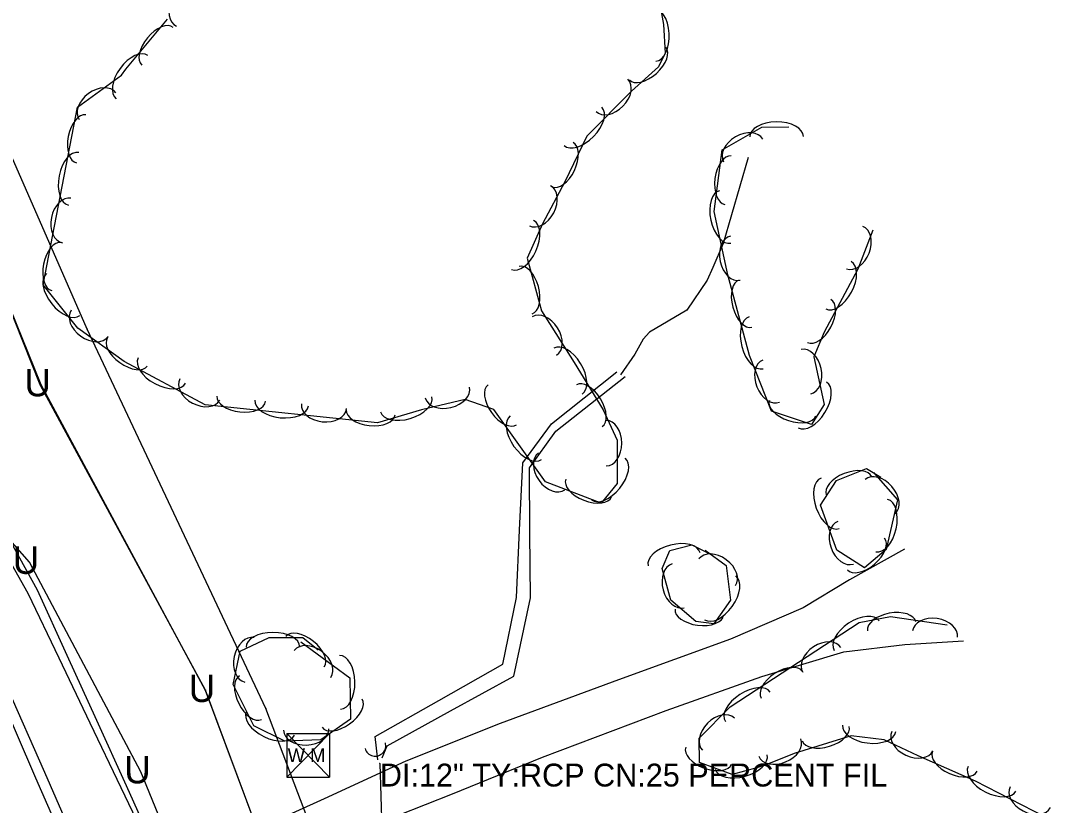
# Model space of a CAD drawing. Extents: x 954793 to 988390, y 1867850 to 1924428.
# Drawn here: x 964997.6 to 965222.6, y 1899765.7 to 1899937.2 of the extents above; entities that cross this region are included whole.
import ezdxf

# ---------------------------------------------------------------- set-up
doc = ezdxf.new("R2010")
doc.units = 0
for name, color, linetype in [('Default', 7, 'Continuous'), ('S_CROSS_DRAIN', 7, 'Continuous'), ('S_DITCHLINE', 7, 'Continuous'), ('S_DRG_PT_SYM', 7, 'Continuous'), ('S_DRIVEWAY', 7, 'Continuous'), ('S_EDGE_PAVEMENT', 7, 'Continuous'), ('S_FIBER_OPTIC_CABLE', 7, 'Continuous'), ('S_SHOULDER', 7, 'Continuous'), ('S_SIDE_DRAIN', 7, 'Continuous'), ('S_SIDE_DRAIN_ANNOT', 7, 'Continuous'), ('S_STREAM', 7, 'Continuous'), ('S_TREE', 7, 'Continuous'), ('S_UNDERGROUND_CABLE', 7, 'Continuous'), ('S_UTL_PT_SYM', 7, 'Continuous'), ('S_WATER_UTILITIES', 7, 'Continuous')]:
    doc.layers.add(name, color=color, linetype=linetype)

msp = doc.modelspace()

# ---------------------------------------------------------------- linework, layer by layer
at = {"layer": 'S_CROSS_DRAIN'}
msp.add_arc((965075.06, 1899778.75), 2.3, 195.7377, 16.0669, dxfattribs=at)
at = {"layer": 'S_DITCHLINE'}
for points in [[(965026.32, 1899755.36), (965019.55, 1899769.53), (965012.77, 1899783.69), (965006, 1899797.85), (964999.22, 1899812.02), (964991.34, 1899825.84), (964983.45, 1899839.67), (964977.86, 1899852.94), (964972.26, 1899866.21), (964966.67, 1899879.48), (964961.07, 1899892.75), (964954.42, 1899908.66), (964947.77, 1899924.57), (964941.11, 1899940.47), (964934.46, 1899956.38), (964927.09, 1899973.92), (964919.72, 1899991.46), (964912.35, 1900008.99), (964904.98, 1900026.53), (964899.8, 1900040.82)], [(965027.15, 1899755.7), (965020.67, 1899769.95), (965014.19, 1899784.21), (965007.71, 1899798.46), (965001.23, 1899812.71), (964993.53, 1899826.7), (964985.84, 1899840.69), (964979.82, 1899853.82), (964973.81, 1899866.96), (964967.79, 1899880.09), (964961.78, 1899893.22), (964955.75, 1899909.26), (964949.73, 1899925.3), (964943.7, 1899941.34), (964937.68, 1899957.38), (964929.93, 1899974.73), (964922.17, 1899992.09), (964914.42, 1900009.44), (964906.67, 1900026.79), (964900.96, 1900041.28)], [(965075.64, 1899775.62), (965075.01, 1899780.71), (965088.97, 1899788.63), (965102.94, 1899796.55), (965105.91, 1899811.09), (965106.6, 1899825.83), (965107.3, 1899840.57), (965113.6, 1899849.09), (965127.88, 1899860.44)], [(965076.56, 1899776.06), (965077.66, 1899778.73), (965091.51, 1899786.32), (965105.36, 1899793.9), (965108.95, 1899811.05), (965108.86, 1899825.24), (965108.76, 1899839.44), (965114.51, 1899847.45), (965129.67, 1899859.44)]]:
    msp.add_lwpolyline(points, dxfattribs=at)
at = {"layer": 'S_DRG_PT_SYM'}
msp.add_lwpolyline([(965076.07, 1899774.81), (965076.07, 1899774.86), (965076.07, 1899774.81), (965076.02, 1899774.81), (965076.07, 1899774.81), (965076.07, 1899774.76), (965076.07, 1899774.81), (965076.12, 1899774.81)], dxfattribs=at)
at = {"layer": 'S_DRIVEWAY'}
for points in [[(965190.73, 1899821.69), (965178.72, 1899814.96), (965168.54, 1899808.89), (965152.66, 1899802.03), (965128.23, 1899793.11), (965102.33, 1899783.62), (965081.71, 1899775.32), (965063.92, 1899767.13), (965044.28, 1899758.24), (965033.55, 1899754.37)], [(965038.61, 1899743.06), (965052.77, 1899750.75), (965068.67, 1899759.66), (965080.14, 1899763.52), (965091.95, 1899768.23), (965111.63, 1899776.26), (965138.64, 1899786.44), (965159.54, 1899793.86), (965177.42, 1899799.22), (965190.78, 1899800.84), (965203.59, 1899801.64)]]:
    msp.add_lwpolyline(points, dxfattribs=at)
at = {"layer": 'S_EDGE_PAVEMENT'}
msp.add_lwpolyline([(965056.6, 1899643.95), (965049.43, 1899660.48), (965041.73, 1899678.21), (965032.84, 1899698.63), (965023.94, 1899719.05), (965016.6, 1899735.79), (965009.26, 1899752.54), (965000.91, 1899771.65), (964992.57, 1899790.77), (964984.95, 1899808.26), (964977.34, 1899825.76), (964968.39, 1899846.47), (964959.44, 1899867.18), (964951.66, 1899885.11), (964943.88, 1899903.04), (964934.93, 1899923.61), (964925.98, 1899944.18)], dxfattribs=at)
at = {"layer": 'S_FIBER_OPTIC_CABLE'}
for p, q in [((965001.85, 1899857.6), (964980.65, 1899910.38)), ((965037.96, 1899790.89), (965001.85, 1899857.6)), ((965073.22, 1899696.48), (965037.96, 1899790.89))]:
    msp.add_line(p, q, dxfattribs=at)
at = {"layer": 'S_SHOULDER'}
msp.add_lwpolyline([(965011.03, 1899754.16), (965002.84, 1899772.86), (964994.65, 1899791.56), (964987.01, 1899809.04), (964979.37, 1899826.51), (964970.32, 1899847.22), (964961.26, 1899867.93), (964953.37, 1899885.83), (964945.48, 1899903.72), (964936.59, 1899924.37), (964927.7, 1899945.01), (964920.2, 1899962.04), (964912.7, 1899979.08), (964903.65, 1900000.26), (964894.61, 1900021.44), (964885.7, 1900041.46), (964876.79, 1900061.49), (964869.66, 1900077.69), (964862.53, 1900093.89), (964862.02, 1900095.03)], dxfattribs=at)
at = {"layer": 'S_SIDE_DRAIN'}
msp.add_line((965076.07, 1899774.81), (965076.66, 1899756.68), dxfattribs=at)
at = {"layer": 'S_STREAM'}
msp.add_lwpolyline([(965156.55, 1899907.27), (965151.09, 1899888.51), (965148.84, 1899883.25), (965147.56, 1899880.47), (965143.15, 1899873.91), (965135.02, 1899869.11), (965133.62, 1899867.57), (965131.78, 1899864.29), (965128.68, 1899859.76)], dxfattribs=at)
at = {"layer": 'S_TREE'}
for points in [[(965135.69, 1899949.33), (965138.04, 1899936.36), (965138.42, 1899930.08), (965136.97, 1899927.12), (965131.06, 1899921.82), (965121.32, 1899911.97), (965116.52, 1899901.94), (965111.64, 1899892.78), (965108.23, 1899885.26), (965111.36, 1899873.78), (965118.51, 1899862.48), (965124.88, 1899852.12), (965127.92, 1899845.5), (965127.93, 1899836.07), (965124.42, 1899831.73), (965112.28, 1899836.43), (965100.96, 1899852.18), (965094.68, 1899854.43), (965085.14, 1899852.11), (965075.53, 1899849.29), (965037.93, 1899853.26), (965020.23, 1899862.68), (965010.05, 1899869.97), (965002.48, 1899879.47), (965010.01, 1899918.26), (965019.62, 1899925.29), (965020.57, 1899926.59), (965029.68, 1899937.54)], [(965183.81, 1899891.39), (965180.54, 1899882.85), (965173.13, 1899869.09), (965170.91, 1899863.74), (965173.15, 1899853.33), (965170.41, 1899848.9), (965161.65, 1899851.82), (965156.82, 1899864.03), (965152.08, 1899881.67), (965149.11, 1899895.49), (965150.89, 1899908.96), (965159.55, 1899913.93), (965165.44, 1899913.99)], [(965183.92, 1899838.46), (965189.17, 1899832.47), (965186.73, 1899821.64), (965182, 1899817.6), (965175.91, 1899821.45), (965172.35, 1899831.32), (965175.82, 1899836.71), (965182.42, 1899839.33), (965185.53, 1899837.42)], [(965147.16, 1899821.48), (965151.74, 1899818.13), (965152.69, 1899810.55), (965149.02, 1899805.39), (965145.09, 1899805.89), (965139.63, 1899810.53), (965137.77, 1899817.43), (965139.45, 1899821.41), (965144.26, 1899822.62), (965147.73, 1899820.85)], [(965221.5, 1899763.12), (965206.2, 1899771.01), (965193.73, 1899776.5), (965186.26, 1899779.98), (965179.07, 1899780.87), (965166.6, 1899777.03), (965160.28, 1899774.45), (965158.42, 1899773.9), (965153.07, 1899772.43), (965145.89, 1899775.05), (965145.87, 1899780.41), (965152.63, 1899787.24), (965180.82, 1899805.67), (965187.67, 1899806.94), (965200.01, 1899805.17)], [(965058.78, 1899801.46), (965069.48, 1899793.56), (965069.66, 1899784.56), (965063.17, 1899779.98), (965055.27, 1899779.73), (965048.53, 1899783.05), (965044, 1899792.11), (965045.54, 1899799.38), (965051.88, 1899802.38), (965059.21, 1899802.41), (965062.62, 1899799.68)]]:
    msp.add_lwpolyline(points, dxfattribs=at)
for centre, major_axis, ratio in [((965033.65, 1899940.52), (-2.05, -4.51), 0.685311), ((965136.05, 1899934.21), (-0.35, 5.86), 0.55008), ((965027.5, 1899931.61), (-3.42, -4.11), 0.540699), ((965021.94, 1899924.87), (-3.46, -4.74), 0.55008), ((965134.57, 1899927.83), (3.98, 3.57), 0.540699), ((965014.39, 1899918.51), (-4, -2.93), 0.685311), ((965126.78, 1899920.88), (3.48, 3.52), 0.685311), ((965120.45, 1899914.11), (4.12, 4.17), 0.55008), ((965010.83, 1899911.35), (-1.02, -5.25), 0.540699), ((965162.75, 1899911.84), (-5.87, -0.06), 0.55008), ((965155.46, 1899908.83), (-4.3, -2.47), 0.685311), ((965115.97, 1899905.72), (2.31, 4.82), 0.540699), ((965009.14, 1899902.65), (-1.12, -5.76), 0.55008), ((965152.16, 1899902.33), (-0.7, -5.3), 0.540699), ((965111.06, 1899896.76), (2.33, 4.37), 0.685311), ((965007.63, 1899893.51), (-0.94, -4.86), 0.685311), ((965151.54, 1899894.29), (1.23, -5.74), 0.55008), ((965107.23, 1899888.18), (2.42, 5.35), 0.55008), ((965179.82, 1899887.61), (1.77, 4.63), 0.685311), ((965005.41, 1899883.45), (-1.02, -5.25), 0.540699), ((965153.74, 1899885.29), (1.04, -4.84), 0.685311), ((965176.27, 1899879.39), (2.78, 5.17), 0.55008), ((965107.93, 1899878.31), (-1.4, 5.16), 0.540699), ((965006.88, 1899877.35), (3.66, -4.59), 0.55008), ((965155.98, 1899875.35), (1.39, -5.16), 0.540699), ((965172.07, 1899871.58), (2.53, 4.71), 0.540699), ((965012.67, 1899871.02), (4.03, -2.88), 0.685311), ((965112.03, 1899868.25), (-2.65, 4.19), 0.685311), ((965158.28, 1899866.79), (1.52, -5.67), 0.55008), ((965020.9, 1899864.81), (4.35, -3.11), 0.540699), ((965117.18, 1899860.59), (-3.07, 5), 0.55008), ((965169.17, 1899860.48), (-1.04, 4.84), 0.685311), ((965028.44, 1899860.72), (5.18, -2.76), 0.55008), ((965161.6, 1899858.42), (1.82, -4.61), 0.685311), ((965036.73, 1899856.6), (4.37, -2.33), 0.685311), ((965102.82, 1899853.23), (3.12, -4.34), 0.540699), ((965121.83, 1899853.03), (-2.8, 4.55), 0.540699), ((965170.59, 1899853.23), (3.09, 4.99), 0.55008), ((965045.79, 1899854.57), (5.32, -0.56), 0.540699), ((965090.81, 1899855.94), (4.82, 1.17), 0.685311), ((965054.61, 1899853.64), (5.84, -0.62), 0.55008), ((965063.84, 1899852.92), (4.93, -0.52), 0.685311), ((965081.81, 1899853.35), (5.63, 1.65), 0.55008), ((965166.25, 1899852.52), (5.07, -1.69), 0.540699), ((965074.06, 1899851.58), (5.32, -0.56), 0.540699), ((965107.99, 1899846.03), (3.42, -4.77), 0.55008), ((965125.54, 1899844.86), (-0.01, 4.96), 0.685311), ((965113.61, 1899838.67), (2.89, -4.02), 0.685311), ((965125.98, 1899837.04), (3.69, 4.56), 0.55008), ((965174.46, 1899831.72), (1.99, -5.52), 0.55008), ((965178.57, 1899835.52), (-4.97, -1.97), 0.540699), ((965185.39, 1899833.16), (-3.27, 3.73), 0.685311), ((965121.68, 1899835.06), (4.99, -1.93), 0.540699), ((965185.73, 1899826.84), (1.29, 5.72), 0.55008), ((965177.85, 1899823.1), (1.68, -4.66), 0.685311), ((965182.29, 1899820.64), (4.06, 3.48), 0.540699), ((965140.36, 1899819.45), (-5.69, -1.43), 0.55008), ((965149.76, 1899816.63), (-4, 2.92), 0.685311), ((965141.25, 1899813.67), (1.29, -4.78), 0.685311), ((965150.44, 1899811.05), (3.4, 4.78), 0.55008), ((965145.87, 1899807.93), (5.3, -0.67), 0.540699), ((965187.91, 1899804.83), (-5.26, -0.97), 0.540699), ((965180.26, 1899802.78), (-4.91, -3.21), 0.55008), ((965197.38, 1899803.14), (-4.91, 0.7), 0.685311), ((965052.71, 1899800.27), (-5.87, -0.02), 0.55008), ((965059.73, 1899799.28), (-4.18, 3.34), 0.540699), ((965047.57, 1899797.5), (-1.03, -4.85), 0.685311), ((965172.66, 1899797.49), (-4.15, -2.71), 0.685311), ((965061.36, 1899796.6), (-3.99, 2.94), 0.685311), ((965067.38, 1899792.6), (-0.12, 5.87), 0.55008), ((965163.89, 1899792.07), (-4.47, -2.93), 0.540699), ((965047.81, 1899789.23), (2.39, -4.78), 0.540699), ((965156.47, 1899787.22), (-4.91, -3.21), 0.55008), ((965067.8, 1899785.84), (4.37, 3.08), 0.540699), ((965052.17, 1899783.62), (5.27, -2.59), 0.55008), ((965150.06, 1899781.26), (-3.48, -3.52), 0.685311), ((965182.98, 1899782.53), (5.82, -0.72), 0.55008), ((965059.96, 1899782.26), (4.95, 0.16), 0.685311), ((965173.49, 1899781.37), (5.11, 1.57), 0.540699), ((965192.43, 1899779.73), (4.49, -2.1), 0.685311), ((965163.44, 1899778.32), (4.59, 1.88), 0.685311), ((965147.92, 1899776.56), (5.02, -1.83), 0.540699), ((965155.03, 1899775.17), (5.66, 1.56), 0.55008), ((965201.68, 1899775.31), (4.89, -2.15), 0.540699), ((965209.84, 1899771.52), (5.22, -2.69), 0.55008), ((965218.18, 1899767.5), (4.4, -2.27), 0.685311)]:
    msp.add_ellipse(centre, major_axis=major_axis, ratio=ratio, start_param=3.141593, end_param=6.283185, dxfattribs=at)
at = {"layer": 'S_UNDERGROUND_CABLE'}
for p, q in [((965002.03, 1899857.63), (964980.65, 1899910.41)), ((965037.94, 1899790.83), (965002.03, 1899857.63)), ((964999.48, 1899818.84), (964986.46, 1899833.47)), ((965023.84, 1899773.05), (964999.48, 1899818.84)), ((965073.2, 1899696.47), (965037.94, 1899790.83)), ((965036.5, 1899742.18), (965023.84, 1899773.05))]:
    msp.add_line(p, q, dxfattribs=at)
at = {"layer": 'S_UTL_PT_SYM'}
for points in [[(965012.11, 1899869.8), (965012.11, 1899869.85), (965012.11, 1899869.8), (965012.06, 1899869.8), (965012.11, 1899869.8), (965012.11, 1899869.75), (965012.11, 1899869.8), (965012.16, 1899869.8)], [(965001.85, 1899857.6), (965001.85, 1899857.65), (965001.85, 1899857.6), (965001.8, 1899857.6), (965001.85, 1899857.6), (965001.85, 1899857.55), (965001.85, 1899857.6), (965001.9, 1899857.6)], [(965037.96, 1899790.89), (965037.96, 1899790.94), (965037.96, 1899790.89), (965037.91, 1899790.89), (965037.96, 1899790.89), (965037.96, 1899790.84), (965037.96, 1899790.89), (965038.01, 1899790.89)], [(965051.15, 1899786.88), (965051.15, 1899786.93), (965051.15, 1899786.88), (965051.1, 1899786.88), (965051.15, 1899786.88), (965051.15, 1899786.83), (965051.15, 1899786.88), (965051.2, 1899786.88)]]:
    msp.add_lwpolyline(points, dxfattribs=at)
at = {"layer": 'S_WATER_UTILITIES'}
for p, q in [((965012.11, 1899869.8), (964982.87, 1899936.46)), ((965051.15, 1899786.88), (965012.11, 1899869.8)), ((965077.66, 1899717.22), (965051.15, 1899786.88)), ((965055.72, 1899781.38), (965065.06, 1899781.38)), ((965055.72, 1899781.38), (965055.72, 1899771.89)), ((965055.72, 1899781.38), (965065.06, 1899771.89)), ((965065.06, 1899781.38), (965055.72, 1899771.89)), ((965065.06, 1899781.38), (965065.06, 1899771.89)), ((965055.72, 1899771.89), (965065.06, 1899771.89))]:
    msp.add_line(p, q, dxfattribs=at)

# ---------------------------------------------------------------- texts
at = {"layer": 'Default'}
for p in [(964998.41, 1899855.09), (964995.85, 1899816.29), (965034.31, 1899788.28), (965020.21, 1899770.5)]:
    msp.add_text('U', height=6, rotation=360, dxfattribs=at).set_placement(p)
at = {"layer": 'S_SIDE_DRAIN_ANNOT'}
msp.add_text('DI:12" TY:RCP CN:25 PERCENT FIL', height=5, dxfattribs=at).set_placement((965076.07, 1899769.81))
at = {"layer": 'S_WATER_UTILITIES'}
msp.add_text('W M', height=3, rotation=360, dxfattribs=at).set_placement((965055.93, 1899775.14))

doc.saveas('drawing.dxf')
